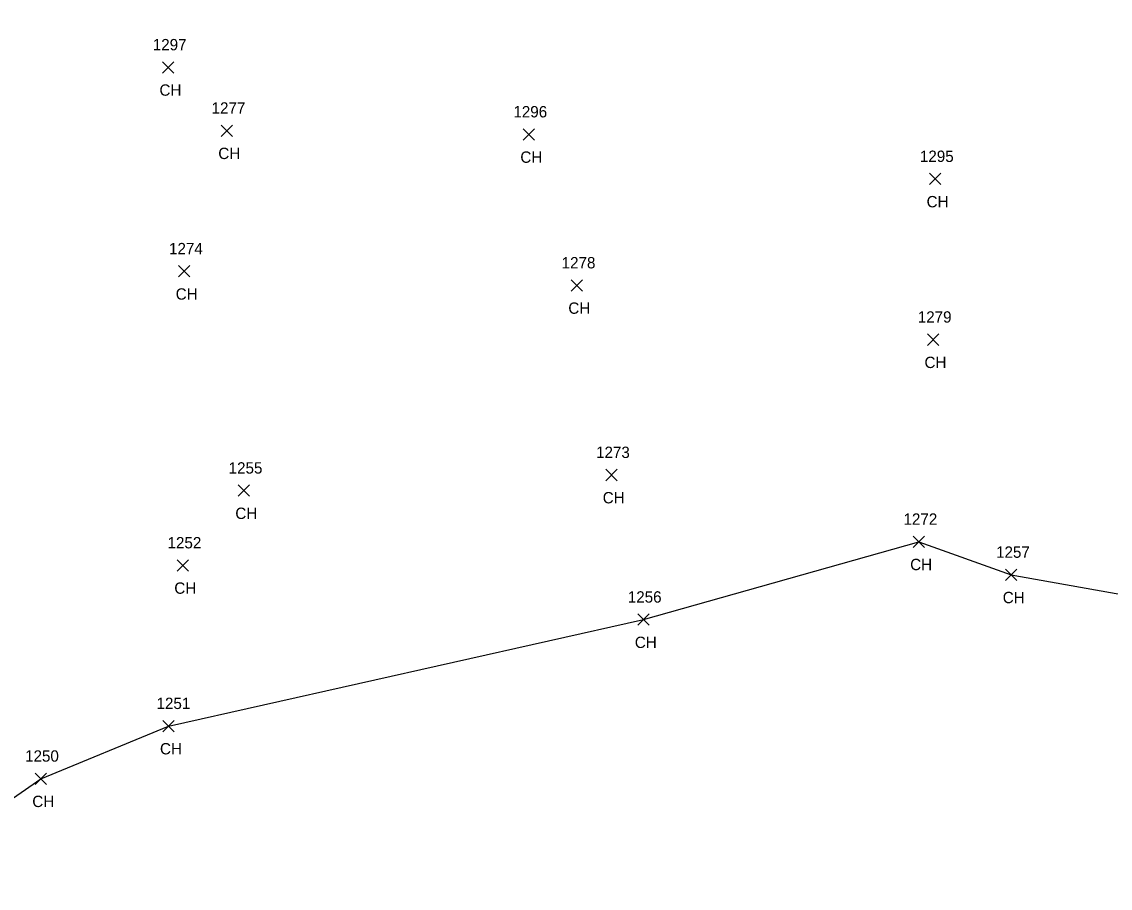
# Model space of a CAD drawing. Extents: x 1715662 to 1717487, y 887396 to 890004.
# Drawn here: x 1716912.5 to 1717104.2, y 888039 to 888191.7 of the extents above; entities that cross this region are included whole.
import ezdxf

# ---------------------------------------------------------------- set-up
doc = ezdxf.new("R2010")
doc.units = 0
for name, color, linetype in [('L_A', 7, 'Continuous'), ('L_I', 7, 'Continuous'), ('L_TIC', 7, 'Continuous'), ('LSOGP', 7, 'Continuous')]:
    doc.layers.add(name, color=color, linetype=linetype)

msp = doc.modelspace()

# ---------------------------------------------------------------- linework, layer by layer
at = {"layer": 'L_TIC'}
for points in [[(1716937.26, 888182.67), (1716939.26, 888184.67)], [(1716939.26, 888182.67), (1716937.26, 888184.67)], [(1716947.62, 888171.51), (1716949.62, 888173.51)], [(1716949.62, 888171.51), (1716947.62, 888173.51)], [(1717000.83, 888170.85), (1717002.83, 888172.85)], [(1717002.83, 888170.85), (1717000.83, 888172.85)], [(1717072.37, 888163), (1717074.37, 888165)], [(1717074.37, 888163), (1717072.37, 888165)], [(1716940.12, 888146.73), (1716942.12, 888148.73)], [(1716942.12, 888146.73), (1716940.12, 888148.73)], [(1717009.27, 888144.24), (1717011.27, 888146.24)], [(1717011.27, 888144.24), (1717009.27, 888146.24)], [(1717072, 888134.68), (1717074, 888136.68)], [(1717074, 888134.68), (1717072, 888136.68)], [(1717015.34, 888110.83), (1717017.34, 888112.83)], [(1717017.34, 888110.83), (1717015.34, 888112.83)], [(1716950.62, 888108.08), (1716952.62, 888110.08)], [(1716952.62, 888108.08), (1716950.62, 888110.08)], [(1717069.48, 888099.06), (1717071.48, 888101.06)], [(1717071.48, 888099.06), (1717069.48, 888101.06)], [(1716939.87, 888094.9), (1716941.87, 888096.9)], [(1716941.87, 888094.9), (1716939.87, 888096.9)], [(1717085.78, 888093.24), (1717087.78, 888095.24)], [(1717087.78, 888093.24), (1717085.78, 888095.24)], [(1717020.98, 888085.34), (1717022.98, 888087.34)], [(1717022.98, 888085.34), (1717020.98, 888087.34)], [(1716937.35, 888066.59), (1716939.35, 888068.59)], [(1716939.35, 888066.59), (1716937.35, 888068.59)], [(1716914.86, 888057.31), (1716916.86, 888059.31)], [(1716916.86, 888057.31), (1716914.86, 888059.31)]]:
    msp.add_lwpolyline(points, dxfattribs=at)
at = {"layer": 'LSOGP'}
msp.add_lwpolyline([(1716693.25, 888191.71), (1716736.98, 888184.04), (1716770.27, 888178.02), (1716763.17, 888137.56), (1716826.34, 888067.38), (1716829.21, 888067.6), (1716859.62, 888068.07), (1716863.39, 888065.91), (1716887.49, 888062.62), (1716888.08, 888039.01), (1716915.87, 888058.3), (1716938.35, 888067.59), (1717021.98, 888086.34), (1717070.48, 888100.06), (1717086.78, 888094.24), (1717129.67, 888086.63)], dxfattribs=at)

# ---------------------------------------------------------------- texts
at = {"layer": 'L_A'}
for p in [(1716936.75, 888178.67), (1716947.11, 888167.51), (1717000.31, 888166.85), (1717071.86, 888159), (1716939.61, 888142.73), (1717008.76, 888140.24), (1717071.49, 888130.68), (1717014.82, 888106.83), (1716950.11, 888104.08), (1717068.97, 888095.06), (1716939.36, 888090.9), (1717085.27, 888089.24), (1717020.47, 888081.34), (1716936.84, 888062.59), (1716914.35, 888053.31)]:
    msp.add_text('CH', height=2, dxfattribs=at).set_placement(p)
at = {"layer": 'L_I'}
for s, p in [('1297', (1716935.57, 888186.67)), ('1277', (1716945.93, 888175.51)), ('1296', (1716999.08, 888174.85)), ('1295', (1717070.68, 888167)), ('1274', (1716938.43, 888150.73)), ('1278', (1717007.58, 888148.24)), ('1279', (1717070.3, 888138.68)), ('1273', (1717013.64, 888114.83)), ('1255', (1716948.93, 888112.08)), ('1272', (1717067.79, 888103.06)), ('1252', (1716938.17, 888098.9)), ('1257', (1717084.09, 888097.24)), ('1256', (1717019.23, 888089.34)), ('1251', (1716936.23, 888070.59)), ('1250', (1716913.08, 888061.31))]:
    msp.add_text(s, height=2, dxfattribs=at).set_placement(p)

doc.saveas('drawing.dxf')
